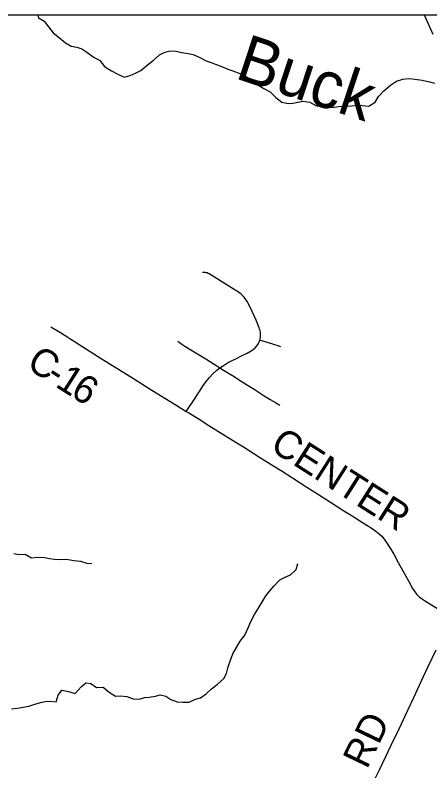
# Model space of a CAD drawing. Extents: x 0 to 34, y 0 to 22.
# Drawn here: x 3.757 to 4.6, y 18.891 to 20.425 of the extents above; entities that cross this region are included whole.
import ezdxf

# ---------------------------------------------------------------- set-up
doc = ezdxf.new("R2010")
doc.units = 0
for name, color, linetype in [('Default', 7, 'Continuous'), ('GM_X_County_Road', 7, 'Continuous'), ('GM_X_County_Road_Text', 7, 'Continuous'), ('GM_X_Minor_River', 7, 'Continuous'), ('GM_X_Minor_River_Text', 7, 'Continuous'), ('GM_X_State_Route', 7, 'Continuous'), ('GM_X_Township_Road', 7, 'Continuous'), ('GM_X_Township_Road_Text', 7, 'Continuous'), ('SH_Cut_Line', 7, 'Continuous')]:
    doc.layers.add(name, color=color, linetype=linetype)

msp = doc.modelspace()

# ---------------------------------------------------------------- linework, layer by layer
at = {"layer": 'Default'}
msp.add_lwpolyline([(8.3334, 17.361), (8.3935, 18.0719), (8.4126, 18.2788), (8.4989, 19.2757), (8.562, 20.012), (8.6014, 20.4252), (3.5682, 20.4252), (3.5424, 20.1754), (3.5231, 19.8516), (3.5169, 19.7823), (3.5125, 19.7343), (3.5092, 19.6961), (3.5066, 19.6647), (3.4966, 19.5464), (3.4903, 19.4759), (3.4748, 19.2963), (3.47, 19.2407), (3.2768, 17.1355)], dxfattribs=at)
at = {"layer": 'GM_X_County_Road'}
for points in [[(3.83, 19.7925), (3.8493, 19.7811), (3.8855, 19.7582), (3.9322, 19.7286), (3.9975, 19.6877), (4.0295, 19.6675), (4.0612, 19.6478), (4.0855, 19.6327), (4.1051, 19.6208)], [(4.1051, 19.6208), (4.1099, 19.6179), (4.1289, 19.6062), (4.1511, 19.5924), (4.2043, 19.5593), (4.2212, 19.5489), (4.2537, 19.5281), (4.281, 19.5109), (4.2995, 19.4994), (4.3205, 19.4861), (4.3497, 19.4672), (4.3718, 19.4533), (4.398, 19.4366), (4.4253, 19.4194), (4.4421, 19.4087), (4.463, 19.3953), (4.4803, 19.3843), (4.4901, 19.3778), (4.4969, 19.3725), (4.5021, 19.3674), (4.5069, 19.3618), (4.512, 19.3548), (4.5193, 19.3434), (4.5264, 19.331), (4.5356, 19.3141), (4.5512, 19.2865), (4.5569, 19.2755), (4.5644, 19.2618), (4.5691, 19.2544), (4.5735, 19.2491), (4.5781, 19.2448), (4.5831, 19.2409), (4.5909, 19.2357), (4.6152, 19.2207)]]:
    msp.add_lwpolyline(points, dxfattribs=at)
at = {"layer": 'GM_X_Minor_River'}
for points in [[(3.8038, 20.4252), (3.8047, 20.42), (3.8164, 20.413), (3.8249, 20.4014), (3.8349, 20.3894), (3.8476, 20.3789), (3.8595, 20.3688), (3.8712, 20.3621), (3.8829, 20.3604), (3.8927, 20.3568), (3.9032, 20.3497), (3.9159, 20.3403), (3.9291, 20.3332), (3.9391, 20.3209), (3.953, 20.3123), (3.9657, 20.3055), (3.9789, 20.2992), (3.9907, 20.3024), (4.003, 20.3078), (4.0126, 20.3126), (4.0257, 20.3234), (4.038, 20.333), (4.0504, 20.3445), (4.06, 20.3493), (4.0699, 20.3517), (4.0821, 20.353), (4.0953, 20.3493), (4.1086, 20.3475), (4.1188, 20.3454), (4.1323, 20.3391), (4.1455, 20.3324), (4.1556, 20.3288), (4.1654, 20.3251), (4.1753, 20.3219), (4.1896, 20.3155), (4.1997, 20.3119), (4.2141, 20.3067), (4.2242, 20.3019), (4.2362, 20.2945), (4.2489, 20.2844), (4.2624, 20.2761), (4.2752, 20.2698), (4.2871, 20.2582), (4.2991, 20.2488), (4.3119, 20.2455), (4.3214, 20.2465), (4.3314, 20.2485), (4.342, 20.2506), (4.356, 20.2484), (4.3684, 20.2421), (4.3798, 20.2392), (4.3923, 20.2382), (4.4056, 20.2383), (4.4151, 20.2397), (4.428, 20.2405), (4.4406, 20.2414), (4.4516, 20.2424), (4.4626, 20.2418), (4.4755, 20.2404), (4.4886, 20.2488), (4.4952, 20.2601), (4.5065, 20.2713), (4.5196, 20.2828), (4.5319, 20.2909), (4.5449, 20.2952), (4.5575, 20.2969), (4.5692, 20.2951), (4.584, 20.2929), (4.5987, 20.2896), (4.6093, 20.2871)], [(3.7546, 19.3326), (3.7645, 19.3305), (3.7778, 19.331), (3.7909, 19.3239), (3.8038, 19.3252), (3.8167, 19.3245), (3.8269, 19.3221), (3.8376, 19.3211), (3.8489, 19.3205), (3.8618, 19.321), (3.8766, 19.3184), (3.8899, 19.317), (3.9031, 19.3126), (3.9129, 19.3124)], [(3.7499, 19.0175), (3.7624, 19.0184), (3.7739, 19.0205), (3.7849, 19.0229), (3.7952, 19.0261), (3.8086, 19.0304), (3.8181, 19.0321), (3.828, 19.0327), (3.8409, 19.0317), (3.845, 19.0453), (3.852, 19.0554), (3.8656, 19.0521), (3.8796, 19.0484), (3.8912, 19.0622), (3.9009, 19.0703), (3.9111, 19.069), (3.9224, 19.0608), (3.936, 19.0613), (3.9487, 19.0508), (3.9615, 19.0433), (3.9714, 19.0439), (3.9842, 19.0421), (3.9971, 19.0377), (4.0103, 19.037), (4.0199, 19.0403), (4.0294, 19.0412), (4.0423, 19.0429), (4.0519, 19.0457), (4.0636, 19.0432), (4.0734, 19.0365), (4.0862, 19.0314), (4.0983, 19.0307), (4.1112, 19.0309), (4.1239, 19.0367), (4.1342, 19.0395), (4.1457, 19.0476), (4.1562, 19.0577), (4.1677, 19.0666), (4.1813, 19.0788), (4.1864, 19.089), (4.1901, 19.1026), (4.1949, 19.1161), (4.1997, 19.1286), (4.2068, 19.1417), (4.2147, 19.1545), (4.224, 19.1668), (4.2308, 19.1815), (4.2363, 19.1947), (4.2435, 19.2086), (4.2505, 19.2195), (4.2588, 19.233), (4.2666, 19.2465), (4.2744, 19.2566), (4.283, 19.2663), (4.295, 19.2793), (4.3057, 19.2848), (4.3164, 19.2892), (4.3281, 19.2999), (4.3313, 19.312)]]:
    msp.add_lwpolyline(points, dxfattribs=at)
at = {"layer": 'GM_X_State_Route'}
msp.add_lwpolyline([(4.6066, 20.3858), (4.5888, 20.4252)], dxfattribs=at)
at = {"layer": 'GM_X_Township_Road'}
for points in [[(4.2549, 19.7658), (4.2554, 19.768), (4.2559, 19.7722), (4.256, 19.777), (4.2555, 19.7812), (4.2548, 19.785), (4.254, 19.7878), (4.2532, 19.7907), (4.2519, 19.7942), (4.2467, 19.8061), (4.2385, 19.8235), (4.2325, 19.8365), (4.2285, 19.8441), (4.2249, 19.8498), (4.2214, 19.8541), (4.2165, 19.8587), (4.2112, 19.8628), (4.2023, 19.8684), (4.1655, 19.8915), (4.1512, 19.9001), (4.1496, 19.901), (4.1473, 19.9019), (4.1456, 19.9024), (4.1435, 19.9028), (4.1417, 19.9029), (4.1379, 19.9028)], [(4.0878, 19.7637), (4.096, 19.7577), (4.1022, 19.7535), (4.1144, 19.7458), (4.1449, 19.7274), (4.1691, 19.7122), (4.1735, 19.7095)], [(4.1735, 19.7095), (4.1804, 19.7143), (4.1884, 19.7192), (4.1966, 19.7237), (4.2067, 19.7286), (4.2173, 19.7336), (4.229, 19.7394), (4.2365, 19.7436), (4.2406, 19.7463), (4.2446, 19.75), (4.2487, 19.7545), (4.2518, 19.759), (4.2538, 19.7634), (4.2549, 19.7658)], [(4.2549, 19.7658), (4.2604, 19.7642), (4.2822, 19.7574), (4.2911, 19.7545), (4.2965, 19.7527)], [(4.1051, 19.6208), (4.1077, 19.6247), (4.1217, 19.646), (4.1298, 19.6584), (4.1319, 19.6614), (4.1382, 19.6714), (4.1455, 19.6815), (4.1522, 19.6897), (4.1591, 19.697), (4.1673, 19.7047), (4.1735, 19.7095)], [(4.1735, 19.7095), (4.1872, 19.7008), (4.1988, 19.6935), (4.2145, 19.6836), (4.2295, 19.6745), (4.2431, 19.6658), (4.2615, 19.6542), (4.2757, 19.6453), (4.2864, 19.639), (4.2953, 19.6333)], [(4.4786, 18.8554), (4.4966, 18.8923), (4.5104, 18.9207), (4.5255, 18.9521), (4.5325, 18.9666), (4.5558, 19.0161), (4.5671, 19.0403), (4.5864, 19.0813), (4.5962, 19.1035), (4.6125, 19.137)]]:
    msp.add_lwpolyline(points, dxfattribs=at)
at = {"layer": 'SH_Cut_Line'}
msp.add_lwpolyline([(2.9696, 13.6252), (9.0621, 13.6252), (9.0621, 20.4252), (3.5682, 20.4252), (3.5424, 20.1754), (3.5231, 19.8516), (3.5169, 19.7823), (3.5125, 19.7343), (3.5092, 19.6961), (3.5066, 19.6647), (3.4966, 19.5464), (3.4903, 19.4759), (3.4748, 19.2963), (3.47, 19.2407), (3.2768, 17.1355), (3.2667, 16.919), (3.1974, 16.1596), (3.1343, 15.4291), (3.0617, 14.6751), (3.0457, 14.4958), (3.0429, 14.4692)], close=True, dxfattribs=at)

# ---------------------------------------------------------------- texts
at = {"layer": 'GM_X_County_Road_Text'}
for s, height, rotation, p in [('C', 0.0568, 327.2009, (3.7779, 19.7105)), ('-', 0.0568, 327.2545, (3.8171, 19.6851)), ('1', 0.0568, 327.4622, (3.8369, 19.6724)), ('6', 0.0568, 328.516, (3.8674, 19.653)), ('CENTER', 0.05682, 327.4598, (4.2726, 19.5439))]:
    msp.add_text(s, height=height, rotation=rotation, dxfattribs=at).set_placement(p)
at = {"layer": 'GM_X_Minor_River_Text'}
msp.add_text('Buck', height=0.09469, rotation=341.5905, dxfattribs=at).set_placement((4.2013, 20.2979))
at = {"layer": 'GM_X_Township_Road_Text'}
msp.add_text('RD', height=0.05682, rotation=64.3029, dxfattribs=at).set_placement((4.472, 18.8931))

doc.saveas('drawing.dxf')
